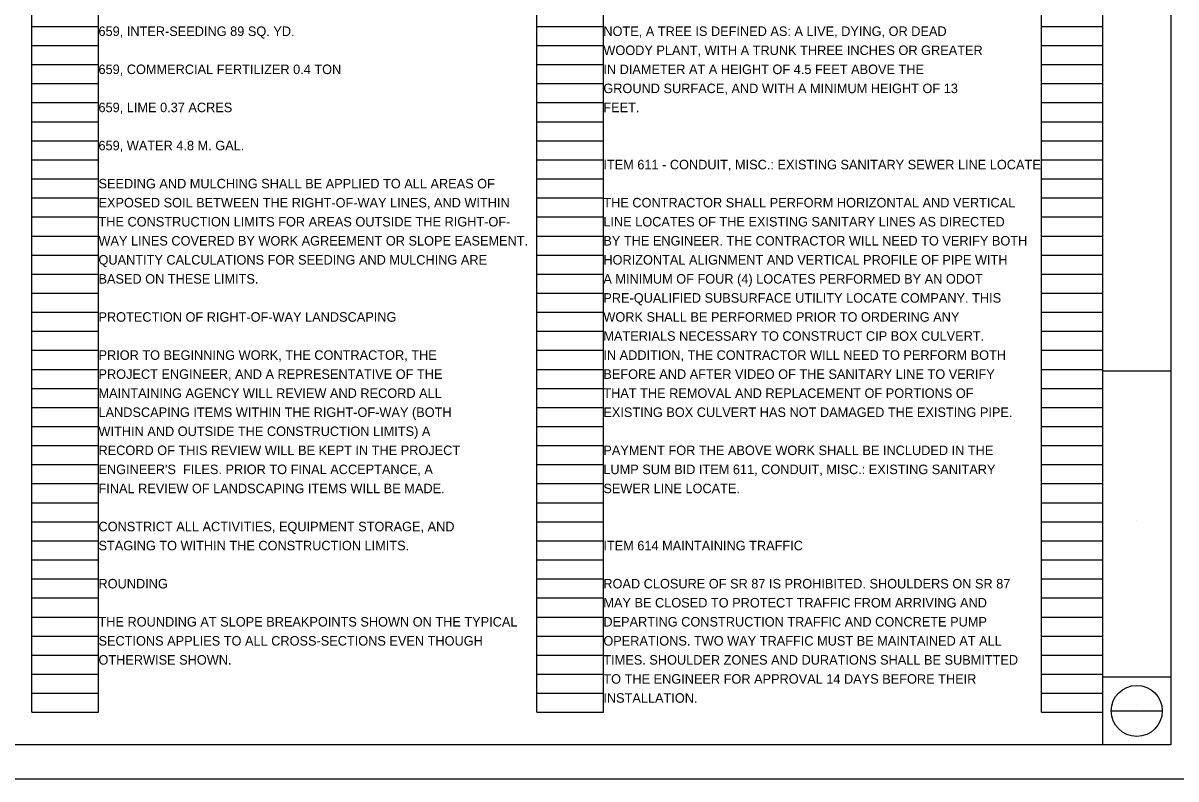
# Model space of a CAD drawing. Extents: x 0 to 50.5, y 0 to 22.
# Drawn here: x 16.63 to 33.58, y 0 to 11.11 of the extents above; entities that cross this region are included whole.
import ezdxf

# ---------------------------------------------------------------- set-up
doc = ezdxf.new("R2010")
doc.units = 0
for name, color, linetype in [('SC_Scratch1', 7, 'Continuous'), ('SH_Border', 7, 'Continuous'), ('SH_Cut_Line', 7, 'Continuous'), ('SH_Data', 7, 'Continuous'), ('SH_Text', 7, 'Continuous')]:
    doc.layers.add(name, color=color, linetype=linetype)

msp = doc.modelspace()

# ---------------------------------------------------------------- linework, layer by layer
at = {"layer": 'SC_Scratch1'}
for p, q in [((16.76, 0.98), (16.76, 21.14)), ((17.74, 0.98), (17.74, 21.14)), ((24.18, 0.98), (24.18, 21.14)), ((25.16, 0.98), (25.16, 21.14)), ((31.6, 0.98), (31.6, 21.14)), ((32.5, 0.98), (32.5, 21.14)), ((16.76, 11.06), (17.74, 11.06)), ((24.18, 11.06), (25.16, 11.06)), ((31.6, 11.06), (32.5, 11.06)), ((16.76, 10.78), (17.74, 10.78)), ((24.18, 10.78), (25.16, 10.78)), ((31.6, 10.78), (32.5, 10.78)), ((16.76, 10.5), (17.74, 10.5)), ((24.18, 10.5), (25.16, 10.5)), ((31.6, 10.5), (32.5, 10.5)), ((16.76, 10.22), (17.74, 10.22)), ((24.18, 10.22), (25.16, 10.22)), ((31.6, 10.22), (32.5, 10.22)), ((16.76, 9.94), (17.74, 9.94)), ((24.18, 9.94), (25.16, 9.94)), ((31.6, 9.94), (32.5, 9.94)), ((16.76, 9.66), (17.74, 9.66)), ((24.18, 9.66), (25.16, 9.66)), ((31.6, 9.66), (32.5, 9.66)), ((16.76, 9.38), (17.74, 9.38)), ((24.18, 9.38), (25.16, 9.38)), ((31.6, 9.38), (32.5, 9.38)), ((16.76, 9.1), (17.74, 9.1)), ((24.18, 9.1), (25.16, 9.1)), ((31.6, 9.1), (32.5, 9.1)), ((16.76, 8.82), (17.74, 8.82)), ((24.18, 8.82), (25.16, 8.82)), ((31.6, 8.82), (32.5, 8.82)), ((16.76, 8.54), (17.74, 8.54)), ((24.18, 8.54), (25.16, 8.54)), ((31.6, 8.54), (32.5, 8.54)), ((16.76, 8.26), (17.74, 8.26)), ((24.18, 8.26), (25.16, 8.26)), ((31.6, 8.26), (32.5, 8.26)), ((16.76, 7.98), (17.74, 7.98)), ((24.18, 7.98), (25.16, 7.98)), ((31.6, 7.98), (32.5, 7.98)), ((16.76, 7.7), (17.74, 7.7)), ((24.18, 7.7), (25.16, 7.7)), ((31.6, 7.7), (32.5, 7.7)), ((16.76, 7.42), (17.74, 7.42)), ((24.18, 7.42), (25.16, 7.42)), ((31.6, 7.42), (32.5, 7.42)), ((16.76, 7.14), (17.74, 7.14)), ((24.18, 7.14), (25.16, 7.14)), ((31.6, 7.14), (32.5, 7.14)), ((16.76, 6.86), (17.74, 6.86)), ((24.18, 6.86), (25.16, 6.86)), ((31.6, 6.86), (32.5, 6.86)), ((16.76, 6.58), (17.74, 6.58)), ((24.18, 6.58), (25.16, 6.58)), ((31.6, 6.58), (32.5, 6.58)), ((16.76, 6.3), (17.74, 6.3)), ((24.18, 6.3), (25.16, 6.3)), ((31.6, 6.3), (32.5, 6.3)), ((16.76, 6.02), (17.74, 6.02)), ((24.18, 6.02), (25.16, 6.02)), ((31.6, 6.02), (32.5, 6.02)), ((16.76, 5.74), (17.74, 5.74)), ((24.18, 5.74), (25.16, 5.74)), ((31.6, 5.74), (32.5, 5.74)), ((16.76, 5.46), (17.74, 5.46)), ((24.18, 5.46), (25.16, 5.46)), ((31.6, 5.46), (32.5, 5.46)), ((16.76, 5.18), (17.74, 5.18)), ((24.18, 5.18), (25.16, 5.18)), ((31.6, 5.18), (32.5, 5.18)), ((16.76, 4.9), (17.74, 4.9)), ((24.18, 4.9), (25.16, 4.9)), ((31.6, 4.9), (32.5, 4.9)), ((16.76, 4.62), (17.74, 4.62)), ((24.18, 4.62), (25.16, 4.62)), ((31.6, 4.62), (32.5, 4.62)), ((16.76, 4.34), (17.74, 4.34)), ((24.18, 4.34), (25.16, 4.34)), ((31.6, 4.34), (32.5, 4.34)), ((16.76, 4.06), (17.74, 4.06)), ((24.18, 4.06), (25.16, 4.06)), ((31.6, 4.06), (32.5, 4.06)), ((16.76, 3.78), (17.74, 3.78)), ((24.18, 3.78), (25.16, 3.78)), ((31.6, 3.78), (32.5, 3.78)), ((16.76, 3.5), (17.74, 3.5)), ((24.18, 3.5), (25.16, 3.5)), ((31.6, 3.5), (32.5, 3.5)), ((16.76, 3.22), (17.74, 3.22)), ((24.18, 3.22), (25.16, 3.22)), ((31.6, 3.22), (32.5, 3.22)), ((16.76, 2.94), (17.74, 2.94)), ((24.18, 2.94), (25.16, 2.94)), ((31.6, 2.94), (32.5, 2.94)), ((16.76, 2.66), (17.74, 2.66)), ((24.18, 2.66), (25.16, 2.66)), ((31.6, 2.66), (32.5, 2.66)), ((16.76, 2.38), (17.74, 2.38)), ((24.18, 2.38), (25.16, 2.38)), ((31.6, 2.38), (32.5, 2.38)), ((16.76, 2.1), (17.74, 2.1)), ((24.18, 2.1), (25.16, 2.1)), ((31.6, 2.1), (32.5, 2.1)), ((16.76, 1.82), (17.74, 1.82)), ((24.18, 1.82), (25.16, 1.82)), ((31.6, 1.82), (32.5, 1.82)), ((16.76, 1.54), (17.74, 1.54)), ((24.18, 1.54), (25.16, 1.54)), ((31.6, 1.54), (32.5, 1.54)), ((16.76, 1.26), (17.74, 1.26)), ((24.18, 1.26), (25.16, 1.26)), ((31.6, 1.26), (32.5, 1.26)), ((16.76, 0.98), (17.74, 0.98)), ((24.18, 0.98), (25.16, 0.98)), ((31.6, 0.98), (32.5, 0.98))]:
    msp.add_line(p, q, dxfattribs=at)
at = {"layer": 'SH_Border'}
for p, q in [((32.5, 0.5), (32.5, 21.5)), ((32.5, 6), (33.5, 6)), ((32.5, 1.5), (33.5, 1.5))]:
    msp.add_line(p, q, dxfattribs=at)
msp.add_lwpolyline([(2, 21.5), (33.5, 21.5), (33.5, 0.5), (2, 0.5)], close=True, dxfattribs=at)
at = {"layer": 'SH_Cut_Line'}
msp.add_lwpolyline([(0, 0), (34, 0), (34, 22), (0, 22)], close=True, dxfattribs=at)
at = {"layer": 'SH_Data'}
for p, q in [((33, 3.792), (33, 3.792)), ((33, 1.085), (33, 1.085)), ((32.625, 1), (33.375, 1)), ((33, 0.745), (33, 0.745))]:
    msp.add_line(p, q, dxfattribs=at)
msp.add_circle((33, 1), 0.375, dxfattribs=at)

# ---------------------------------------------------------------- texts
at = {"layer": 'SH_Text'}
for s, p in [('659, INTER-SEEDING 89 SQ. YD.', (17.74, 10.92)), ('NOTE, A TREE IS DEFINED AS: A LIVE, DYING, OR DEAD', (25.16, 10.92)), ('WOODY PLANT, WITH A TRUNK THREE INCHES OR GREATER', (25.16, 10.64)), ('659, COMMERCIAL FERTILIZER 0.4 TON', (17.74, 10.36)), ('IN DIAMETER AT A HEIGHT OF 4.5 FEET ABOVE THE', (25.16, 10.36)), ('GROUND SURFACE, AND WITH A MINIMUM HEIGHT OF 13', (25.16, 10.08)), ('659, LIME 0.37 ACRES', (17.74, 9.8)), ('FEET.', (25.16, 9.8)), ('659, WATER 4.8 M. GAL.', (17.74, 9.24)), ('ITEM 611 - CONDUIT, MISC.: EXISTING SANITARY SEWER LINE LOCATE', (25.16, 8.96)), ('SEEDING AND MULCHING SHALL BE APPLIED TO ALL AREAS OF', (17.74, 8.68)), ('EXPOSED SOIL BETWEEN THE RIGHT-OF-WAY LINES, AND WITHIN', (17.74, 8.4)), ('THE CONTRACTOR SHALL PERFORM HORIZONTAL AND VERTICAL', (25.16, 8.4)), ('THE CONSTRUCTION LIMITS FOR AREAS OUTSIDE THE RIGHT-OF-', (17.74, 8.12)), ('LINE LOCATES OF THE EXISTING SANITARY LINES AS DIRECTED', (25.16, 8.12)), ('WAY LINES COVERED BY WORK AGREEMENT OR SLOPE EASEMENT.', (17.74, 7.84)), ('BY THE ENGINEER. THE CONTRACTOR WILL NEED TO VERIFY BOTH', (25.16, 7.84)), ('QUANTITY CALCULATIONS FOR SEEDING AND MULCHING ARE', (17.74, 7.56)), ('HORIZONTAL ALIGNMENT AND VERTICAL PROFILE OF PIPE WITH', (25.16, 7.56)), ('BASED ON THESE LIMITS.', (17.74, 7.28)), ('A MINIMUM OF FOUR (4) LOCATES PERFORMED BY AN ODOT', (25.16, 7.28)), ('PRE-QUALIFIED SUBSURFACE UTILITY LOCATE COMPANY. THIS', (25.16, 7)), ('PROTECTION OF RIGHT-OF-WAY LANDSCAPING', (17.74, 6.72)), ('WORK SHALL BE PERFORMED PRIOR TO ORDERING ANY', (25.16, 6.72)), ('MATERIALS NECESSARY TO CONSTRUCT CIP BOX CULVERT.', (25.16, 6.44)), ('PRIOR TO BEGINNING WORK, THE CONTRACTOR, THE', (17.74, 6.16)), ('IN ADDITION, THE CONTRACTOR WILL NEED TO PERFORM BOTH', (25.16, 6.16)), ('PROJECT ENGINEER, AND A REPRESENTATIVE OF THE', (17.74, 5.88)), ('BEFORE AND AFTER VIDEO OF THE SANITARY LINE TO VERIFY', (25.16, 5.88)), ('MAINTAINING AGENCY WILL REVIEW AND RECORD ALL', (17.74, 5.6)), ('THAT THE REMOVAL AND REPLACEMENT OF PORTIONS OF', (25.16, 5.6)), ('LANDSCAPING ITEMS WITHIN THE RIGHT-OF-WAY (BOTH', (17.74, 5.32)), ('EXISTING BOX CULVERT HAS NOT DAMAGED THE EXISTING PIPE.', (25.16, 5.32)), ('WITHIN AND OUTSIDE THE CONSTRUCTION LIMITS) A', (17.74, 5.04)), ('RECORD OF THIS REVIEW WILL BE KEPT IN THE PROJECT', (17.74, 4.76)), ('PAYMENT FOR THE ABOVE WORK SHALL BE INCLUDED IN THE', (25.16, 4.76)), ("ENGINEER'S  FILES. PRIOR TO FINAL ACCEPTANCE, A", (17.74, 4.48)), ('LUMP SUM BID ITEM 611, CONDUIT, MISC.: EXISTING SANITARY', (25.16, 4.48)), ('FINAL REVIEW OF LANDSCAPING ITEMS WILL BE MADE.', (17.74, 4.2)), ('SEWER LINE LOCATE.', (25.16, 4.2)), ('CONSTRICT ALL ACTIVITIES, EQUIPMENT STORAGE, AND', (17.74, 3.64)), ('STAGING TO WITHIN THE CONSTRUCTION LIMITS.', (17.74, 3.36)), ('ITEM 614 MAINTAINING TRAFFIC', (25.16, 3.36)), ('ROUNDING', (17.74, 2.8)), ('ROAD CLOSURE OF SR 87 IS PROHIBITED. SHOULDERS ON SR 87', (25.16, 2.8)), ('MAY BE CLOSED TO PROTECT TRAFFIC FROM ARRIVING AND', (25.16, 2.52)), ('THE ROUNDING AT SLOPE BREAKPOINTS SHOWN ON THE TYPICAL', (17.74, 2.24)), ('DEPARTING CONSTRUCTION TRAFFIC AND CONCRETE PUMP', (25.16, 2.24)), ('SECTIONS APPLIES TO ALL CROSS-SECTIONS EVEN THOUGH', (17.74, 1.96)), ('OPERATIONS. TWO WAY TRAFFIC MUST BE MAINTAINED AT ALL', (25.16, 1.96)), ('OTHERWISE SHOWN.', (17.74, 1.68)), ('TIMES. SHOULDER ZONES AND DURATIONS SHALL BE SUBMITTED', (25.16, 1.68)), ('TO THE ENGINEER FOR APPROVAL 14 DAYS BEFORE THEIR', (25.16, 1.4)), ('INSTALLATION.', (25.16, 1.12))]:
    msp.add_text(s, height=0.14, dxfattribs=at).set_placement(p)

doc.saveas('drawing.dxf')
